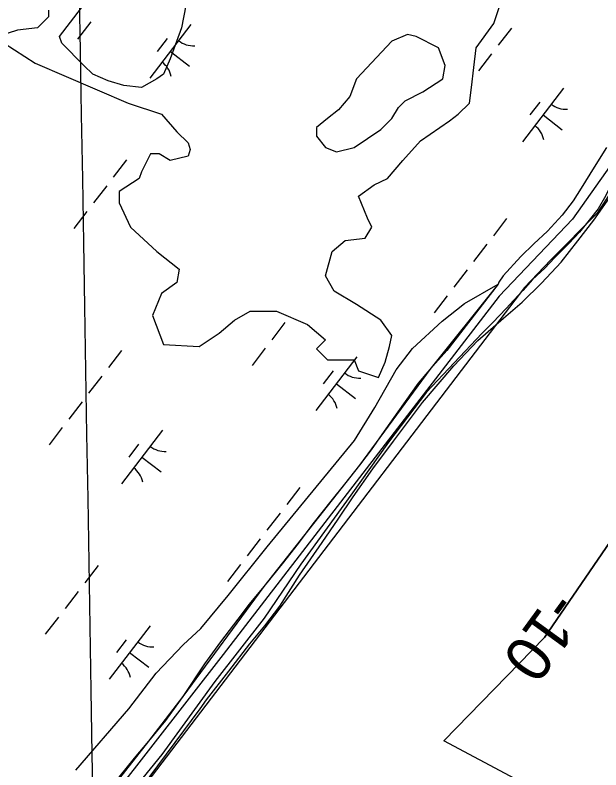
# Model space of a CAD drawing. Extents: x 3879599 to 3900814, y 146526 to 168888.
# Drawn here: x 3893939 to 3894372, y 161718 to 162277 of the extents above; entities that cross this region are included whole.
import ezdxf

# ---------------------------------------------------------------- set-up
doc = ezdxf.new("R2010")
doc.units = 0
for name, color, linetype in [('V-GRID-MAJR', 7, 'Continuous'), ('V-RIVR-EDGE', 7, 'Continuous'), ('V-RIVR-JETY', 7, 'Continuous'), ('V-RIVR-RANG', 7, 'Continuous'), ('V-RRAP-FSHR', 7, 'Continuous'), ('V-TOPO-DPTH', 7, 'Continuous'), ('V-TOPO-MINR', 7, 'Continuous'), ('V-TOPO-SHOR', 7, 'Continuous'), ('V-WETL-SWMP', 7, 'Continuous')]:
    doc.layers.add(name, color=color, linetype=linetype)

msp = doc.modelspace()

# ---------------------------------------------------------------- linework, layer by layer
at = {"layer": 'V-GRID-MAJR'}
msp.add_spline([(3894134.72, 153416.68), (3894080.41, 156663.61), (3893979.03, 162723.86), (3893946.66, 164659.13)], degree=3, dxfattribs=at)
at = {"layer": 'V-RIVR-EDGE'}
msp.add_lwpolyline([(3894996.77, 162983.53), (3894972.23, 162947.83), (3894959.22, 162908.81), (3894952.72, 162865.13), (3894942.49, 162837.26), (3894932.27, 162822.39), (3894915.55, 162820.53), (3894892.32, 162812.17), (3894875.59, 162806.59), (3894862.58, 162797.3), (3894686.03, 162560.35), (3894502.98, 162313.18), (3894441.65, 162241.63), (3894369.17, 162130.13), (3894334.79, 162095.75), (3894315.28, 162075.3), (3893894.35, 161523.35), (3893644.39, 161210.21), (3893630.45, 161202.78), (3893449.25, 161162.82), (3893262.48, 161121.94), (3892618.54, 160989.06), (3892386.24, 160942.6)], dxfattribs=at)
at = {"layer": 'V-RIVR-JETY'}
for points in [[(3894376.08, 162178.96), (3894366.92, 162164.2), (3894357.42, 162148.77), (3894351.31, 162139.38), (3894343.17, 162128.65), (3894332.34, 162116.93), (3894322.2, 162107.56), (3894312.72, 162098.19), (3894299.52, 162083.79), (3894296.47, 162079.09), (3894295.79, 162077.75), (3894257.84, 162028.48), (3894245.31, 162014.41), (3894236.84, 162004.36), (3894221.59, 161983.24), (3894209.72, 161966.48), (3894201.92, 161955.08), (3894193.44, 161943.68), (3894182.26, 161929.6), (3894173.12, 161918.21), (3894158.89, 161900.11), (3894148.04, 161885.7), (3894137.2, 161871.96), (3894122.63, 161853.86), (3894111.79, 161840.79)], [(3894386.65, 162167.04), (3894382.14, 162157.34), (3894375.58, 162143.2), (3894369.87, 162133.52), (3894363.34, 162125.05), (3894356.01, 162116.18), (3894348.27, 162107.71), (3894337.69, 162097.24), (3894330.35, 162089.59), (3894321.4, 162081.13), (3894314.07, 162073.07), (3894307.56, 162065.82), (3894301.85, 162059.77), (3894292.08, 162049.3), (3894283.94, 162041.24), (3894242.81, 161997.73), (3894214.67, 161960.63), (3894186.93, 161921.5), (3894149.81, 161870.27), (3894122.88, 161830.33), (3894086.19, 161783.55), (3894047.03, 161729.5), (3893995.26, 161665.79)], [(3894111.79, 161840.79), (3894103.32, 161829.73), (3894090.44, 161812.97), (3894078.58, 161796.55), (3894062.63, 161772.4), (3894049.75, 161754.63), (3894037.22, 161739.22), (3894026.72, 161726.82), (3894015.2, 161712.75)]]:
    msp.add_lwpolyline(points, dxfattribs=at)
at = {"layer": 'V-RRAP-FSHR'}
msp.add_lwpolyline([(3894988.6, 162989.5), (3894928.15, 162903.5), (3894582.92, 162435.83), (3894412.91, 162213.52), (3894350.95, 162125.82), (3894296.72, 162068.74), (3894092.54, 161803.48), (3893724.45, 161331), (3893640.54, 161218.2), (3893416.13, 161165.56), (3892609.14, 161000)], dxfattribs=at)
at = {"layer": 'V-TOPO-DPTH'}
msp.add_lwpolyline([(3894583.39, 161564.9), (3894255.7, 161739.59), (3894330.09, 161816.04), (3894779.1, 162471.69), (3894959.67, 162614.35), (3894982.55, 162633.86), (3895004.38, 162654.41), (3895024.63, 162676.51), (3895043.83, 162699.66), (3895072.99, 162737.61), (3895076.66, 162742.66), (3895080.14, 162747.83), (3895083.35, 162753.17), (3895086.37, 162758.63), (3895101.79, 162788.37), (3895104.27, 162794.7), (3895105.86, 162801.16), (3895106.1, 162807.8), (3895105.44, 162814.57), (3895407.09, 162684.23)], dxfattribs=at)
at = {"layer": 'V-TOPO-MINR'}
msp.add_lwpolyline([(3894959.67, 162614.35), (3894779.1, 162471.69), (3894330.09, 161816.04), (3894255.7, 161739.59)], dxfattribs=at)
at = {"layer": 'V-TOPO-SHOR'}
for points in [[(3893963.18, 162280.59), (3893963.18, 162275.67), (3893954.99, 162267.47), (3893940.24, 162265.83), (3893925.48, 162260.92)], [(3893930.4, 162256), (3893953.35, 162241.25), (3893999.24, 162221.58), (3894022.19, 162211.74), (3894046.78, 162203.55), (3894058.25, 162190.43), (3894066.45, 162182.24), (3894068.09, 162177.32), (3894066.45, 162172.4), (3894053.33, 162169.13), (3894045.14, 162174.04), (3894038.58, 162174.04), (3894032.03, 162160.93), (3894030.39, 162156.01), (3894015.63, 162146.18), (3894015.63, 162137.98), (3894023.83, 162119.95), (3894043.5, 162101.92), (3894059.89, 162088.81), (3894058.25, 162078.98), (3894046.78, 162070.78), (3894040.22, 162054.39), (3894048.42, 162033.08), (3894074.64, 162031.44), (3894089.39, 162041.28), (3894100.87, 162051.11), (3894112.34, 162057.67), (3894132.01, 162057.67), (3894154.96, 162047.83), (3894168.07, 162036.36), (3894161.51, 162029.8), (3894169.71, 162021.61), (3894181.18, 162021.61), (3894189.38, 162021.61), (3894192.66, 162013.41), (3894207.41, 162008.49), (3894212.33, 162019.97), (3894215.6, 162031.44), (3894217.24, 162039.64), (3894209.05, 162051.11), (3894191.02, 162062.58), (3894174.63, 162072.42), (3894168.07, 162083.89), (3894172.99, 162101.92), (3894182.82, 162110.12), (3894197.57, 162111.76), (3894202.49, 162119.95), (3894199.21, 162126.51), (3894192.66, 162142.9), (3894204.13, 162151.1), (3894213.97, 162156.01), (3894225.44, 162169.13), (3894238.55, 162183.88), (3894259.86, 162198.63), (3894266.42, 162203.55), (3894274.61, 162211.74), (3894276.25, 162223.22), (3894277.89, 162237.97), (3894279.53, 162252.72), (3894292.64, 162270.75), (3894297.56, 162285.5)], [(3894064.81, 162283.86), (3894061.53, 162267.47), (3894053.33, 162244.52), (3894048.42, 162233.05), (3894043.5, 162229.77), (3894032.03, 162223.22), (3894018.91, 162224.86), (3894007.44, 162228.13), (3893995.97, 162233.05), (3893989.41, 162239.61), (3893973.02, 162256), (3893971.38, 162260.92), (3893987.77, 162282.22)], [(3893983.36, 161717.87), (3894022.71, 161763.34), (3894042.82, 161789.57), (3894062.94, 161810.56), (3894076.05, 161822.8), (3894096.16, 161847.29), (3894125.02, 161883.14), (3894189.73, 161961.84), (3894204.6, 161986.32), (3894220.34, 162014.31), (3894232.58, 162030.05), (3894254.44, 162050.16), (3894271.06, 162063.28), (3894295.79, 162077.75), (3894245.31, 162014.41), (3894193.44, 161943.68), (3894122.63, 161853.86), (3894062.63, 161772.4), (3894037.22, 161739.22), (3893954.88, 161634.32)]]:
    msp.add_lwpolyline(points, dxfattribs=at)
msp.add_lwpolyline([(3894217.24, 162257.64), (3894191.02, 162229.77), (3894186.1, 162216.66), (3894177.9, 162206.83), (3894169.71, 162200.27), (3894161.51, 162193.71), (3894161.51, 162187.16), (3894168.07, 162178.96), (3894176.27, 162175.68), (3894189.38, 162178.96), (3894209.05, 162192.07), (3894217.24, 162200.27), (3894222.16, 162208.46), (3894227.08, 162213.38), (3894240.19, 162219.94), (3894254.94, 162229.77), (3894256.58, 162239.61), (3894251.66, 162252.72), (3894235.27, 162260.92), (3894228.72, 162262.55)], close=True, dxfattribs=at)
at = {"layer": 'V-WETL-SWMP'}
for p, q in [((3893994.46, 162271.84), (3893984.71, 162259.15)), ((3894068.62, 162269.81), (3894038.15, 162230.17)), ((3894305.7, 162267.24), (3894295.95, 162254.55)), ((3894050.92, 162259.45), (3894043.61, 162249.93)), ((3894053.38, 162249.99), (3894067.65, 162239.02)), ((3894291.07, 162248.21), (3894281.32, 162235.52)), ((3894344.33, 162222.79), (3894313.86, 162183.14)), ((3894326.63, 162212.43), (3894319.32, 162202.91)), ((3894329.1, 162202.97), (3894343.37, 162192)), ((3894020.89, 162169.61), (3894011.14, 162156.92)), ((3894006.27, 162150.58), (3893996.52, 162137.89)), ((3894366.68, 162125.13), (3894381.78, 162146.51)), ((3893991.64, 162131.55), (3893981.89, 162118.86)), ((3894302.11, 162126.22), (3894292.36, 162113.53)), ((3894354.85, 162109.8), (3894366.68, 162125.13)), ((3894287.49, 162107.19), (3894277.74, 162094.5)), ((3894342.61, 162094.07), (3894354.85, 162109.8)), ((3894327.95, 162078.35), (3894342.61, 162094.07)), ((3894272.87, 162088.16), (3894263.12, 162075.47)), ((3894313.7, 162064.25), (3894327.95, 162078.35)), ((3894258.24, 162069.13), (3894248.49, 162056.44)), ((3894299.87, 162052.58), (3894313.7, 162064.25)), ((3894280.74, 162036.07), (3894299.87, 162052.58)), ((3894138.16, 162049.22), (3894128.41, 162036.54)), ((3894263.22, 162017.13), (3894280.74, 162036.07)), ((3894123.53, 162030.19), (3894113.79, 162017.51)), ((3894017.31, 162028.59), (3894007.56, 162015.9)), ((3894191.41, 162023.81), (3894160.95, 161984.16)), ((3894173.72, 162013.44), (3894166.41, 162003.93)), ((3894239.99, 161990.11), (3894263.22, 162017.13)), ((3894002.68, 162009.56), (3893992.93, 161996.87)), ((3894176.18, 162003.98), (3894190.45, 161993.01)), ((3893988.06, 161990.53), (3893978.31, 161977.84)), ((3894218.38, 161961.47), (3894239.99, 161990.11)), ((3893973.44, 161971.5), (3893963.69, 161958.81)), ((3894047.59, 161969.47), (3894017.13, 161929.83)), ((3894029.9, 161959.11), (3894022.59, 161949.59)), ((3894203.28, 161940.89), (3894218.38, 161961.47)), ((3894032.36, 161949.65), (3894046.63, 161938.68)), ((3894188.59, 161920.31), (3894203.28, 161940.89)), ((3894149.2, 161927.23), (3894139.45, 161914.55)), ((3894177.56, 161903.77), (3894188.59, 161920.31)), ((3894134.58, 161908.2), (3894124.83, 161895.52)), ((3894165.73, 161886.41), (3894177.56, 161903.77)), ((3894119.95, 161889.17), (3894110.2, 161876.49)), ((3894148.99, 161862.2), (3894165.73, 161886.41)), ((3893999.87, 161869.27), (3893990.12, 161856.58)), ((3894105.33, 161870.14), (3894095.58, 161857.46)), ((3894134.29, 161839.19), (3894148.99, 161862.2)), ((3893985.24, 161850.24), (3893975.49, 161837.55)), ((3894123.28, 161824.67), (3894134.29, 161839.19)), ((3893970.62, 161831.21), (3893960.87, 161818.52)), ((3894038.5, 161824.82), (3894008.03, 161785.17)), ((3894112.27, 161811.36), (3894123.28, 161824.67)), ((3894020.81, 161814.46), (3894013.49, 161804.94)), ((3894096.77, 161791.19), (3894112.27, 161811.36)), ((3894023.27, 161805), (3894037.54, 161794.03)), ((3894080.05, 161769.81), (3894096.77, 161791.19)), ((3894075.56, 161763.35), (3894080.05, 161769.81)), ((3894026.2, 161696.95), (3894075.56, 161763.35))]:
    msp.add_line(p, q, dxfattribs=at)
for points in [[(3893963.18, 162280.59), (3893963.18, 162275.67), (3893954.99, 162267.47), (3893940.24, 162265.83), (3893925.48, 162260.92)], [(3893930.4, 162256), (3893953.35, 162241.25), (3893999.24, 162221.58), (3894022.19, 162211.74), (3894046.78, 162203.55), (3894058.25, 162190.43), (3894066.45, 162182.24), (3894068.09, 162177.32), (3894066.45, 162172.4), (3894053.33, 162169.13), (3894045.14, 162174.04), (3894038.58, 162174.04), (3894032.03, 162160.93), (3894030.39, 162156.01), (3894015.63, 162146.18), (3894015.63, 162137.98), (3894023.83, 162119.95), (3894043.5, 162101.92), (3894059.89, 162088.81), (3894058.25, 162078.98), (3894046.78, 162070.78), (3894040.22, 162054.39), (3894048.42, 162033.08), (3894074.64, 162031.44), (3894089.39, 162041.28), (3894100.87, 162051.11), (3894112.34, 162057.67), (3894132.01, 162057.67), (3894154.96, 162047.83), (3894168.07, 162036.36), (3894161.51, 162029.8), (3894169.71, 162021.61), (3894181.18, 162021.61), (3894189.38, 162021.61), (3894192.66, 162013.41), (3894207.41, 162008.49), (3894212.33, 162019.97), (3894215.6, 162031.44), (3894217.24, 162039.64), (3894209.05, 162051.11), (3894191.02, 162062.58), (3894174.63, 162072.42), (3894168.07, 162083.89), (3894172.99, 162101.92), (3894182.82, 162110.12), (3894197.57, 162111.76), (3894202.49, 162119.95), (3894199.21, 162126.51), (3894192.66, 162142.9), (3894204.13, 162151.1), (3894213.97, 162156.01), (3894225.44, 162169.13), (3894238.55, 162183.88), (3894259.86, 162198.63), (3894266.42, 162203.55), (3894274.61, 162211.74), (3894276.25, 162223.22), (3894277.89, 162237.97), (3894279.53, 162252.72), (3894292.64, 162270.75), (3894297.56, 162285.5)], [(3894064.81, 162283.86), (3894061.53, 162267.47), (3894053.33, 162244.52), (3894048.42, 162233.05), (3894043.5, 162229.77), (3894032.03, 162223.22), (3894018.91, 162224.86), (3894007.44, 162228.13), (3893995.97, 162233.05), (3893989.41, 162239.61), (3893973.02, 162256), (3893971.38, 162260.92), (3893987.77, 162282.22)], [(3893983.36, 161717.87), (3894022.71, 161763.34), (3894042.82, 161789.57), (3894062.94, 161810.56), (3894076.05, 161822.8), (3894096.16, 161847.29), (3894125.02, 161883.14), (3894189.73, 161961.84), (3894204.6, 161986.32), (3894220.34, 162014.31), (3894232.58, 162030.05), (3894254.44, 162050.16), (3894271.06, 162063.28), (3894295.79, 162077.75), (3894245.31, 162014.41), (3894193.44, 161943.68), (3894122.63, 161853.86), (3894062.63, 161772.4), (3894037.22, 161739.22), (3893954.88, 161634.32)]]:
    msp.add_lwpolyline(points, dxfattribs=at)
msp.add_lwpolyline([(3894217.24, 162257.64), (3894191.02, 162229.77), (3894186.1, 162216.66), (3894177.9, 162206.83), (3894169.71, 162200.27), (3894161.51, 162193.71), (3894161.51, 162187.16), (3894168.07, 162178.96), (3894176.27, 162175.68), (3894189.38, 162178.96), (3894209.05, 162192.07), (3894217.24, 162200.27), (3894222.16, 162208.46), (3894227.08, 162213.38), (3894240.19, 162219.94), (3894254.94, 162229.77), (3894256.58, 162239.61), (3894251.66, 162252.72), (3894235.27, 162260.92), (3894228.72, 162262.55)], close=True, dxfattribs=at)
for centre, start, end in [((3894070.4, 162271.74), 231.6869, 273.2305), ((3894036.74, 162227.94), 11.6869, 53.2305), ((3894346.11, 162224.72), 231.6869, 273.2305), ((3894312.45, 162180.92), 11.6869, 53.2305), ((3894193.2, 162025.74), 231.6869, 273.2305), ((3894159.54, 161981.94), 11.6869, 53.2305), ((3894049.38, 161971.4), 231.6869, 273.2305), ((3894015.72, 161927.6), 11.6869, 53.2305), ((3894040.29, 161826.75), 231.6869, 273.2305), ((3894006.62, 161782.95), 11.6869, 53.2305)]:
    msp.add_arc(centre, 17.62, start, end, dxfattribs=at)

# ---------------------------------------------------------------- texts
at = {"layer": 'V-RIVR-RANG'}
msp.add_text('-10', height=33.5, rotation=233.9783, dxfattribs=at).set_placement((3894335.78, 161852.34))

doc.saveas('drawing.dxf')
